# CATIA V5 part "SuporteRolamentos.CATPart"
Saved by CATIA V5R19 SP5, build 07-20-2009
Part number: SuporteRolamentos.1
Bounding box of the stored display mesh (mm): x -17.5 to 17.5, y 0 to 19, z -25.5 to 25.5
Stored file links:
  Z:\UA\ATLAS\atlascar\ServoPiloto\dir\suportePotenciometro\V2\potenciometro\SuporteRolamentos.CATPart
  Z:\programs_vbox\Dassault Systemes\B19\intel_a\reffiles\standard\MetricThickPitch.txt
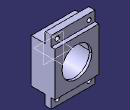
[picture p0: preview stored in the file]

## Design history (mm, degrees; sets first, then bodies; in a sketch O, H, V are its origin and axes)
Body1 (main body)
  Sketch1 on zx-plane, origin (0, 0, 0), H (-1, 0, 0), V (0, 0, 1)
    circle A1 centre (0, 0) radius 13
    line L1 (-17.5, 17.5) -> (17.5, 17.5)
    line L2 (17.5, 17.5) -> (17.5, -17.5)
    line L3 (17.5, -17.5) -> (-17.5, -17.5)
    line L4 (-17.5, -17.5) -> (-17.5, 17.5)
    radius A1 = 13
    distance L1 L3 = 35
    distance L2 L4 = 35
    distance L3 H = 17.5 {= Sketch1.distance(L1 L3) /2}
    distance V L2 = 17.5 {= Sketch1.distance(L2 L4) /2}
    horizontal: L1 H, L3 H
    vertical: L2 V, L4 V
  Pad1: profile Sketch1, direction (0, 1, 0), length 17
  Sketch2 on start face of Pad1, origin (0, 0, 0), H (1, 0, 0), V (0, 0, 1)
    construction circle A1 centre (0, 0) radius 13
    construction line L1 (-17.5, 17.5) -> (17.5, 17.5)
    construction line L2 (17.5, 17.5) -> (17.5, -17.5)
    construction line L3 (17.5, -17.5) -> (-17.5, -17.5)
    construction line L4 (-17.5, -17.5) -> (-17.5, 17.5)
    circle A2 centre (13.5, 13.5) radius 1.25
    point P5 (13.5, 13.5)
    circle A3 centre (-13.5, 13.5) radius 1.25
    circle A4 centre (13.5, -13.5) radius 1.25
    circle A5 centre (-13.5, -13.5) radius 1.25
    radius A1 = 13
    distance L1 L3 = 35
    distance L2 L4 = 35
    distance L3 H = 17.5 {= Sketch2.distance(L1 L3) /2}
    distance V L2 = 17.5 {= Sketch2.distance(L2 L4) /2}
    radius A2 = 1.25
    distance P5 L2 = 4
    distance L1 P5 = 4
    horizontal: L1 H, L3 H
    vertical: L2 V, L4 V
    symmetry: A2 A3 V, A2 A4 H, A3 A5 H
  Pocket1: profile Sketch2, direction (0, 1, 0), length 7
  Sketch3 on end face of Pad1, origin (0, 17, 0), H (-1, 0, 0), V (0, 0, 1)
    circle A1 centre (0, 0) radius 12
    point P1 (0, 0)
    line L1 (-17.5, 17.5) -> (17.5, 17.5)
    line L2 (17.5, 17.5) -> (17.5, -17.5)
    line L3 (17.5, -17.5) -> (-17.5, -17.5)
    line L4 (-17.5, -17.5) -> (-17.5, 17.5)
    reference intersected line E1 (-17.5, 17.5) -> (17.5, 17.5) from face of Pad2
    reference intersected line E2 (17.5, 17.5) -> (17.5, -17.5) from face of Pad2
    reference intersected line E3 (17.5, -17.5) -> (-17.5, -17.5) from face of Pad2
    reference intersected line E4 (-17.5, -17.5) -> (-17.5, 17.5) from face of Pad2
    radius A1 = 12
    coincidence: O P1, L1 E1, E2 L2, E3 L3, L4 E4
    horizontal: L1 H, L3 H
    vertical: L2 V, L4 V
  Pad2: profile Sketch3, direction (0, 1, 0), length 2
  Sketch4 on end face of Pad2, origin (0, 19, 0), H (-1, 0, 0), V (0, 0, 1)
    point P1 (-17.5, 25.5)
    line L1 (-17.5, 25.5) -> (17.5, 25.5)
    line L2 (17.5, 25.5) -> (17.5, 17.5)
    line L3 (17.5, 17.5) -> (-17.5, 17.5)
    line L4 (-17.5, 17.5) -> (-17.5, 25.5)
    point P2 (17.5, 25.5)
    point P3 (17.5, 17.5)
    point P4 (-17.5, 17.5)
    reference projected line E1 (17.5, 17.5) -> (-17.5, 17.5) from edge [face of Pad1 from Sketch1.L1 | end face of Pad1]
    reference projected line E2 (17.5, -17.5) -> (17.5, 17.5) from edge [face of Pad1 from Sketch1.L2 | end face of Pad1]
    reference projected line E3 (-17.5, 17.5) -> (-17.5, -17.5) from edge [face of Pad1 from Sketch1.L4 | end face of Pad1]
    point P5 (-17.5, -25.5)
    point P6 (17.5, -25.5)
    point P7 (17.5, -17.5)
    point P8 (-17.5, -17.5)
    line L5 (-17.5, -25.5) -> (17.5, -25.5)
    line L6 (17.5, -25.5) -> (17.5, -17.5)
    line L7 (17.5, -17.5) -> (-17.5, -17.5)
    line L8 (-17.5, -17.5) -> (-17.5, -25.5)
    length L4 = 8
    horizontal: L1 H, L3 H
    vertical: L2 V, L4 V
    coincidence: E1 L3, E2 L2, L4 E3
    symmetry: P1 P5 H, P2 P6 H, P3 P7 H, P4 P8 H, L1 L5 H, L2 L6 H, L3 L7 H, L4 L8 H
  Pad3: profile Sketch4, direction (0, -1, 0), length 8
  Sketch5 on end face of Pad3, origin (0, 11, 0), H (-1, 0, 0), V (0, 0, 1)
    circle A1 centre (-12.75, 21) radius 1.75
    point P1 (-12.75, 21)
    circle A2 centre (12.75, 21) radius 1.75
    point P2 (12.75, 21)
    axis line L1 (-25.619, 21) -> (25.6957, 21)
    reference projected line E1 (-17.5, 17.5) -> (-17.5, -17.5) from edge [face of Pad1 | face of Pad1]
    reference projected line E2 (17.5, -17.5) -> (17.5, 17.5) from edge [face of Pad1 | face of Pad1]
    circle A3 centre (-12.75, -21) radius 1.75
    circle A4 centre (12.75, -21) radius 1.75
    radius A2 = 1.75
    radius A1 = 1.75 {= Sketch5.radius(A2)}
    distance E1 P1 = 4.75 {= Sketch5.distance(P2 E2)}
    distance P2 E2 = 4.75 {= Sketch5.radius(A2) + 3mm}
    distance L1 H = 21
    horizontal: L1 H
    coincidence: P2 L1, P1 L1
    symmetry: A1 A3 H, A2 A4 H
  Pocket2: profile Sketch5, direction (0, -1, 0), through (limit type 6)
  Sketch6 on face of Pad3, origin (0, 19, 0), H (-1, 0, 0), V (0, 0, 1)
    point P1 (-17.5, 25.5)
    line L1 (-17.5, 25.5) -> (17.5, 25.5)
    line L2 (17.5, 25.5) -> (17.5, 17.5)
    line L3 (17.5, 17.5) -> (-17.5, 17.5)
    line L4 (-17.5, 17.5) -> (-17.5, 25.5)
    point P2 (17.5, 25.5)
    point P3 (17.5, 17.5)
    point P4 (-17.5, 17.5)
    reference projected line E1 (-17.5, 17.5) -> (-17.5, -17.5) from edge [face of Pad3 | face of Pad3]
    reference projected line E2 (17.5, -17.5) -> (17.5, 17.5) from edge [face of Pad3 | face of Pad3]
    point P5 (17.5, -25.5)
    point P6 (-17.5, -25.5)
    line L5 (-17.5, -25.5) -> (17.5, -25.5)
    point P7 (-17.5, -17.5)
    line L6 (-17.5, -17.5) -> (-17.5, -25.5)
    point P8 (17.5, -17.5)
    line L7 (17.5, -17.5) -> (-17.5, -17.5)
    line L8 (17.5, -25.5) -> (17.5, -17.5)
    reference projected line E3 (17.5, 25.5) -> (-17.5, 25.5) from edge [face of Pad3 from Sketch4.L1 | face of Pad3]
    reference intersected line E4 through (0, 17.5) direction (1, 0) from face of Pad2
    horizontal: L1 H, L3 H
    vertical: L2 V, L4 V
    coincidence: E1 L4, E2 L2, L1 E3, L3 E4
    symmetry: P2 P5 H, P1 P6 H, L1 L5 H, P4 P7 H, L4 L6 H, P3 P8 H, L3 L7 H, L2 L8 H
  Pocket3: profile Sketch6, direction (0, -1, 0), length 3
  Thread1: "M3", diameter 3, depth 7, pitch 0.5, on face of Pocket1 from Sketch2.A4, from start face of Pad1
  Thread2: "M3", diameter 3, depth 7, pitch 0.5, on face of Pocket1 from Sketch2.A5, from start face of Pad1
  Thread3: "M3", diameter 3, depth 7, pitch 0.5, on face of Pocket1 from Sketch2.A2, from start face of Pad1
  Thread4: "M3", diameter 3, depth 7, pitch 0.5, on face of Pocket1 from Sketch2.A3, from start face of Pad1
